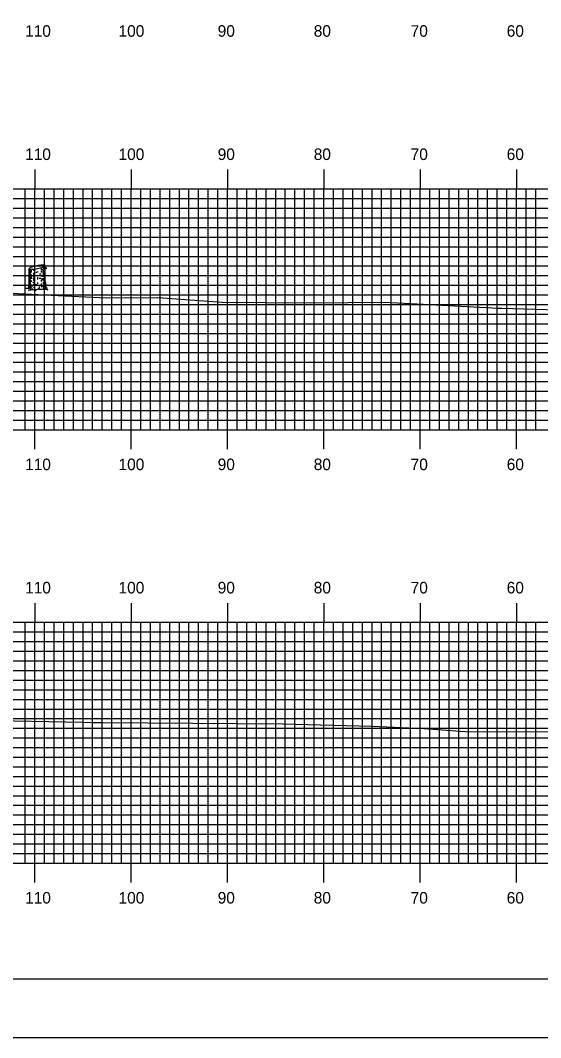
# Model space of a CAD drawing. Extents: x 1772022 to 1772366, y 442591 to 442811.
# Drawn here: x 1772076.6 to 1772130.6, y 442590.5 to 442696.2 of the extents above; entities that cross this region are included whole.
import ezdxf

# ---------------------------------------------------------------- set-up
doc = ezdxf.new("R2010")
doc.units = 0
for name, color, linetype in [('BORDER', 7, 'Continuous'), ('H_V ANNOTATION', 7, 'Continuous'), ('M_Trees_Conifer_Pay', 7, 'Continuous'), ('MAJOR', 7, 'Continuous'), ('MINOR', 7, 'Continuous'), ('PLOT BOUNDARY', 7, 'Continuous'), ('S_Roadway_Centerline', 7, 'Continuous')]:
    doc.layers.add(name, color=color, linetype=linetype)

msp = doc.modelspace()

# ---------------------------------------------------------------- linework, layer by layer
at = {"layer": 'BORDER'}
msp.add_lwpolyline([(1772038.49, 442596.67), (1772358.49, 442596.67), (1772358.49, 442806.67), (1772038.49, 442806.67)], close=True, dxfattribs=at)
at = {"layer": 'M_Trees_Conifer_Pay'}
for p, q in [((1772077.49, 442668.66), (1772077.49, 442670.38)), ((1772077.54, 442670.34), (1772077.54, 442669.87)), ((1772077.59, 442670.33), (1772077.59, 442670.23)), ((1772077.59, 442670.16), (1772077.59, 442669.96)), ((1772077.72, 442670.32), (1772077.72, 442670.09)), ((1772077.72, 442670.05), (1772077.72, 442669.98)), ((1772077.94, 442670.34), (1772077.94, 442670.18)), ((1772078.35, 442670.11), (1772078.35, 442670.02)), ((1772078.74, 442670.39), (1772078.74, 442670.19)), ((1772078.74, 442670.13), (1772078.74, 442670.04)), ((1772078.96, 442670.58), (1772078.96, 442670.36)), ((1772078.96, 442670.27), (1772078.96, 442670.22)), ((1772079.02, 442670.09), (1772078.97, 442670.03)), ((1772079.08, 442670.64), (1772079.08, 442670.48)), ((1772079.08, 442670.41), (1772079.08, 442670.29)), ((1772079.08, 442670.1), (1772079.08, 442669.76)), ((1772079.15, 442669.07), (1772079.15, 442670.72)), ((1772077.54, 442669.81), (1772077.54, 442669.5)), ((1772077.54, 442669.45), (1772077.54, 442668.96)), ((1772077.59, 442669.9), (1772077.59, 442669.7)), ((1772077.59, 442669.65), (1772077.59, 442669.32)), ((1772077.59, 442669.26), (1772077.59, 442669.13)), ((1772077.59, 442669.03), (1772077.59, 442668.65)), ((1772077.72, 442669.57), (1772077.72, 442669.43)), ((1772077.72, 442669.16), (1772077.72, 442669.02)), ((1772077.94, 442669.94), (1772077.94, 442669.7)), ((1772077.94, 442669.46), (1772077.94, 442669.31)), ((1772077.94, 442669.26), (1772077.94, 442669.09)), ((1772078.35, 442669.5), (1772078.35, 442669.42)), ((1772078.35, 442669.4), (1772078.35, 442669.25)), ((1772078.74, 442669.69), (1772078.74, 442669.59)), ((1772078.74, 442669.22), (1772078.74, 442669.07)), ((1772078.96, 442669.89), (1772078.96, 442669.76)), ((1772078.96, 442669.65), (1772078.96, 442669.54)), ((1772078.96, 442669.4), (1772078.96, 442669.26)), ((1772078.96, 442669.03), (1772078.96, 442668.86)), ((1772079.08, 442669.73), (1772079.08, 442669.56)), ((1772079.08, 442669.52), (1772079.08, 442669.3)), ((1772079.08, 442669.27), (1772079.08, 442669.19)), ((1772079.08, 442669.15), (1772079.08, 442668.98)), ((1772077.54, 442668.91), (1772077.54, 442668.66)), ((1772077.72, 442668.76), (1772077.72, 442668.66)), ((1772077.72, 442668.27), (1772077.88, 442668.33)), ((1772077.94, 442668.81), (1772077.94, 442668.66)), ((1772078.16, 442668.2), (1772078.03, 442668.27)), ((1772078.35, 442668.96), (1772078.35, 442668.81)), ((1772078.74, 442668.84), (1772078.74, 442668.75))]:
    msp.add_line(p, q, dxfattribs=at)
for points in [[(1772078.94, 442670.18), (1772078.91, 442670.09), (1772078.9, 442670.02), (1772078.93, 442669.96)], [(1772078.97, 442670.21), (1772079.01, 442670.14), (1772079.05, 442670.2), (1772079.11, 442670.26), (1772079.2, 442670.46), (1772079.27, 442670.51), (1772079.3, 442670.51)], [(1772078.98, 442669.96), (1772079.02, 442670.09), (1772079.08, 442670.2), (1772079.12, 442670.27), (1772079.18, 442670.42)], [(1772079.2, 442670.45), (1772079.27, 442670.45), (1772079.35, 442670.36)], [(1772079.15, 442669.07), (1772079.2, 442668.81), (1772079.22, 442668.53), (1772079.28, 442668.41), (1772079.41, 442668.38), (1772079.18, 442668.34), (1772079.18, 442668.34), (1772079.19, 442668.29), (1772079.44, 442668.2), (1772079.16, 442668.21), (1772078.81, 442668.23), (1772078.49, 442668.22), (1772078.49, 442668.31), (1772078.34, 442668.22), (1772078.16, 442668.2), (1772078.18, 442668.13), (1772077.91, 442668.18), (1772077.69, 442668.15), (1772077.4, 442668.17), (1772077.69, 442668.22), (1772077.72, 442668.27), (1772077.56, 442668.32), (1772077.32, 442668.33), (1772077.08, 442668.33), (1772077.42, 442668.39), (1772077.46, 442668.47), (1772077.49, 442668.66)], [(1772077.67, 442669.69), (1772077.66, 442669.78), (1772077.71, 442669.76), (1772077.71, 442669.66)], [(1772078.81, 442669.29), (1772078.82, 442669.21), (1772078.87, 442669.22), (1772078.85, 442669.39)], [(1772077.54, 442668.61), (1772077.52, 442668.53), (1772077.5, 442668.44)], [(1772077.61, 442668.59), (1772077.62, 442668.48), (1772077.57, 442668.39), (1772077.56, 442668.32)], [(1772077.78, 442668.62), (1772077.78, 442668.49), (1772077.69, 442668.39)], [(1772078, 442668.38), (1772078.07, 442668.47), (1772078.1, 442668.61)], [(1772078.49, 442668.31), (1772078.57, 442668.45), (1772078.58, 442668.55)], [(1772078.74, 442668.68), (1772078.75, 442668.55), (1772078.83, 442668.51)], [(1772079.02, 442668.29), (1772079.01, 442668.42), (1772078.93, 442668.55)], [(1772078.98, 442668.78), (1772079.05, 442668.68), (1772079.06, 442668.5), (1772079.18, 442668.34)], [(1772079.08, 442668.93), (1772079.08, 442668.78), (1772079.13, 442668.71), (1772079.14, 442668.51)]]:
    msp.add_lwpolyline(points, dxfattribs=at)
for centre, radius, start, end in [((1772077.54, 442670.37), 0.0527, 146.7194, 156.5158), ((1772077.52, 442670.38), 0.0314, 156.5158, 169.2194), ((1772077.52, 442670.38), 0.0264, 169.2194, 180.0315), ((1772077.51, 442670.38), 0.0226, 180.0315, 191.7194), ((1772077.51, 442670.38), 0.0226, 191.7194, 203.4074), ((1772077.51, 442670.38), 0.0264, 203.4074, 214.2194), ((1772077.52, 442670.38), 0.0314, 214.2194, 226.923), ((1772077.52, 442670.2), 0.0334, 163.9485, 180), ((1772077.52, 442670.2), 0.0334, 180, 196.0515), ((1772077.53, 442670.2), 0.0441, 196.0515, 210), ((1772077.55, 442670.21), 0.0624, 210, 228.7494), ((1772077.56, 442670.35), 0.0817, 132.3887, 146.7194), ((1772077.53, 442670.4), 0.0527, 226.923, 236.7194), ((1772077.55, 442670.42), 0.0817, 236.7194, 251.0501), ((1772077.68, 442670.23), 0.251, 124.2194, 132.3887), ((1772077.62, 442670.3), 0.172, 228.7494, 240), ((1772077.6, 442670.58), 0.251, 251.0501, 259.2194), ((1772077.82, 442670.64), 0.571, 240, 240.3367), ((1772077.99, 442669.77), 0.802, 108.0594, 124.2194), ((1772077.71, 442671.12), 0.802, 259.2194, 275.3794), ((1772077.82, 442670.64), 0.571, 246.8597, 257.9846), ((1772079.34, 442665.61), 5.18, 101.7194, 108.0594), ((1772077.3, 442675.48), 5.18, 275.3794, 281.7194), ((1772078.32, 442674.39), 4.12, 264.6955, 266.7331), ((1772079.34, 442665.61), 5.18, 95.3794, 101.7194), ((1772077.3, 442675.48), 5.18, 281.7194, 288.0594), ((1772078.32, 442674.16), 4.12, 275.7849, 277.0558), ((1772078.32, 442674.39), 4.12, 276.238, 278.1032), ((1772078.93, 442669.97), 0.802, 79.2194, 95.3794), ((1772078.65, 442671.32), 0.802, 288.0594, 304.2194), ((1772078.82, 442670.87), 0.571, 278.1032, 284.3667), ((1772078.82, 442671.03), 0.571, 284.4317, 292.4132), ((1772079.04, 442670.51), 0.251, 71.0501, 79.2194), ((1772078.82, 442670.87), 0.571, 297.0237, 300), ((1772078.96, 442670.87), 0.251, 304.2194, 312.3887), ((1772079.02, 442670.68), 0.172, 300, 311.2506), ((1772079.02, 442670.53), 0.172, 300, 311.2506), ((1772079.09, 442670.67), 0.0817, 56.7194, 71.0501), ((1772079.08, 442670.74), 0.0817, 312.3887, 326.7194), ((1772079.09, 442670.6), 0.0624, 311.2506, 330), ((1772079.09, 442670.45), 0.0624, 311.2506, 330), ((1772079.11, 442670.7), 0.0527, 46.923, 56.7194), ((1772079.12, 442670.71), 0.0314, 34.2194, 46.923), ((1772079.13, 442670.71), 0.0264, 23.4074, 34.2194), ((1772079.13, 442670.72), 0.0226, 11.7194, 23.4074), ((1772079.13, 442670.72), 0.0264, 349.2194, 0.0315), ((1772079.13, 442670.72), 0.0226, 0.0315, 11.7194), ((1772079.12, 442670.72), 0.0314, 336.5158, 349.2194), ((1772079.1, 442670.73), 0.0527, 326.7194, 336.5158), ((1772079.12, 442670.59), 0.0334, 343.9485, 354.2151), ((1772079.11, 442670.59), 0.0441, 330, 343.9485), ((1772079.11, 442670.44), 0.0441, 330, 343.9485), ((1772079.12, 442670.43), 0.0334, 343.9485, 354.2151), ((1772077.52, 442669.76), 0.0334, 163.9485, 180), ((1772077.52, 442669.76), 0.0334, 180, 196.0515), ((1772077.53, 442669.76), 0.0441, 196.0515, 210), ((1772077.55, 442669.77), 0.0624, 210, 228.7494), ((1772077.52, 442669.55), 0.0334, 163.9485, 180), ((1772077.52, 442669.55), 0.0334, 180, 196.0515), ((1772077.53, 442669.55), 0.0441, 196.0515, 210), ((1772077.55, 442669.56), 0.0624, 210, 228.7494), ((1772077.52, 442669.31), 0.0334, 163.9485, 180), ((1772077.52, 442669.31), 0.0334, 180, 196.0515), ((1772077.53, 442669.31), 0.0441, 196.0515, 210), ((1772077.55, 442669.32), 0.0624, 210, 228.7494), ((1772077.52, 442669.11), 0.0334, 163.9485, 180), ((1772077.62, 442669.85), 0.172, 228.7494, 240), ((1772077.62, 442669.64), 0.172, 228.7494, 240), ((1772077.62, 442669.4), 0.172, 228.7494, 240), ((1772077.82, 442670.43), 0.571, 240, 247.0587), ((1772077.82, 442670.19), 0.571, 240, 240.3367), ((1772077.82, 442669.98), 0.571, 240, 246.8597), ((1772077.82, 442669.75), 0.571, 240, 246.8597), ((1772077.81, 442669.56), 0.571, 241.2369, 248.0268), ((1772077.82, 442669.98), 0.571, 259.2707, 261.8968), ((1772078.32, 442673.5), 4.12, 261.8968, 263.1474), ((1772078.32, 442673.71), 4.12, 264.081, 266.6676), ((1772078.32, 442673.27), 4.12, 264.716, 266.3193), ((1772078.32, 442674.16), 4.12, 268.0751, 270), ((1772078.32, 442674.16), 4.12, 270, 270.3581), ((1772078.32, 442673.5), 4.12, 270, 270.3581), ((1772078.32, 442673.5), 4.12, 273.1493, 275.4569), ((1772078.32, 442673.95), 4.12, 273.7052, 275.9504), ((1772078.32, 442673.71), 4.12, 277.6125, 278.1032), ((1772078.82, 442670.19), 0.571, 278.1032, 286.9296), ((1772078.82, 442670.43), 0.571, 284.4493, 297.0429), ((1772078.82, 442669.75), 0.571, 285.3983, 297.1896), ((1772078.82, 442669.55), 0.571, 289.2907, 300), ((1772078.82, 442670.19), 0.571, 297.1896, 300), ((1772078.82, 442669.98), 0.571, 297.1896, 300), ((1772079.02, 442669.85), 0.172, 300, 311.2506), ((1772079.02, 442669.64), 0.172, 300, 311.2506), ((1772079.02, 442669.21), 0.172, 300, 311.2506), ((1772079.09, 442669.77), 0.0624, 311.2506, 330), ((1772079.09, 442669.56), 0.0624, 311.2506, 330), ((1772079.09, 442669.12), 0.0624, 311.2506, 330), ((1772079.12, 442669.99), 0.0334, 343.9485, 354.2151), ((1772079.11, 442669.76), 0.0441, 330, 343.9485), ((1772079.12, 442669.76), 0.0334, 343.9485, 354.2151), ((1772079.11, 442669.55), 0.0441, 330, 343.9485), ((1772079.12, 442669.55), 0.0334, 343.9485, 354.2151), ((1772079.12, 442669.11), 0.0334, 343.9485, 354.2151), ((1772079.11, 442669.11), 0.0441, 330, 343.9485), ((1772077.52, 442668.92), 0.0334, 163.9485, 180), ((1772077.52, 442668.92), 0.0334, 180, 196.0515), ((1772077.53, 442668.92), 0.0441, 196.0515, 210), ((1772077.55, 442668.93), 0.0624, 210, 228.7494), ((1772077.52, 442668.69), 0.0334, 163.9485, 180), ((1772077.52, 442668.69), 0.0334, 180, 196.0515), ((1772077.53, 442668.7), 0.0441, 196.0515, 210), ((1772077.55, 442668.71), 0.0624, 210, 228.7494), ((1772077.62, 442669.01), 0.172, 228.7494, 240), ((1772077.62, 442668.79), 0.172, 228.7494, 240), ((1772077.82, 442669.35), 0.571, 240, 246.8597), ((1772077.82, 442669.13), 0.571, 240, 244.5314), ((1772078.32, 442672.65), 4.12, 262.4438, 263.512), ((1772078.32, 442673.07), 4.12, 263.4991, 265.8397), ((1772078.32, 442672.87), 4.12, 267.8117, 270), ((1772078.32, 442672.87), 4.12, 270, 270.1328), ((1772078.32, 442672.87), 4.12, 275.7849, 276.7896), ((1772078.32, 442672.65), 4.12, 277.3684, 278.1032), ((1772078.82, 442669.13), 0.571, 278.1032, 281.637), ((1772078.82, 442669.35), 0.571, 288.5067, 297.2721), ((1772079.02, 442668.79), 0.172, 300, 311.2506), ((1772079.09, 442668.71), 0.0624, 311.2506, 330), ((1772079.11, 442668.7), 0.0441, 330, 343.9485), ((1772079.12, 442668.69), 0.0334, 343.9485, 354.2151)]:
    msp.add_arc(centre, radius, start, end, dxfattribs=at)
at = {"layer": 'MAJOR'}
for p, q in [((1772078.09, 442680.67), (1772078.09, 442678.67)), ((1772088.09, 442680.67), (1772088.09, 442678.67)), ((1772098.09, 442680.67), (1772098.09, 442678.67)), ((1772108.09, 442680.67), (1772108.09, 442678.67)), ((1772118.09, 442680.67), (1772118.09, 442678.67)), ((1772128.09, 442680.67), (1772128.09, 442678.67)), ((1772048.09, 442678.67), (1772328.09, 442678.67)), ((1772048.09, 442678.67), (1772328.09, 442678.67)), ((1772078.09, 442653.67), (1772078.09, 442678.67)), ((1772088.09, 442653.67), (1772088.09, 442678.67)), ((1772098.09, 442653.67), (1772098.09, 442678.67)), ((1772108.09, 442653.67), (1772108.09, 442678.67)), ((1772118.09, 442653.67), (1772118.09, 442678.67)), ((1772128.09, 442653.67), (1772128.09, 442678.67)), ((1772048.09, 442673.67), (1772328.09, 442673.67)), ((1772048.09, 442668.67), (1772328.09, 442668.67)), ((1772048.09, 442663.67), (1772328.09, 442663.67)), ((1772048.09, 442658.67), (1772328.09, 442658.67)), ((1772048.09, 442653.67), (1772328.09, 442653.67)), ((1772048.09, 442653.67), (1772328.09, 442653.67)), ((1772078.09, 442651.66), (1772078.09, 442653.67)), ((1772088.09, 442651.66), (1772088.09, 442653.67)), ((1772098.09, 442651.66), (1772098.09, 442653.67)), ((1772108.09, 442651.66), (1772108.09, 442653.67)), ((1772118.09, 442651.66), (1772118.09, 442653.67)), ((1772128.09, 442651.66), (1772128.09, 442653.67)), ((1772078.09, 442635.67), (1772078.09, 442633.67)), ((1772088.09, 442635.67), (1772088.09, 442633.67)), ((1772098.09, 442635.67), (1772098.09, 442633.67)), ((1772108.09, 442635.67), (1772108.09, 442633.67)), ((1772118.09, 442635.67), (1772118.09, 442633.67)), ((1772128.09, 442635.67), (1772128.09, 442633.67)), ((1772048.09, 442633.67), (1772328.09, 442633.67)), ((1772048.09, 442633.67), (1772328.09, 442633.67)), ((1772078.09, 442608.67), (1772078.09, 442633.67)), ((1772088.09, 442608.67), (1772088.09, 442633.67)), ((1772098.09, 442608.67), (1772098.09, 442633.67)), ((1772108.09, 442608.67), (1772108.09, 442633.67)), ((1772118.09, 442608.67), (1772118.09, 442633.67)), ((1772128.09, 442608.67), (1772128.09, 442633.67)), ((1772048.09, 442628.67), (1772328.09, 442628.67)), ((1772048.09, 442623.67), (1772328.09, 442623.67)), ((1772048.09, 442618.67), (1772328.09, 442618.67)), ((1772048.09, 442613.67), (1772328.09, 442613.67)), ((1772048.09, 442608.67), (1772328.09, 442608.67)), ((1772048.09, 442608.67), (1772328.09, 442608.67)), ((1772078.09, 442606.66), (1772078.09, 442608.67)), ((1772088.09, 442606.66), (1772088.09, 442608.67)), ((1772098.09, 442606.66), (1772098.09, 442608.67)), ((1772108.09, 442606.66), (1772108.09, 442608.67)), ((1772118.09, 442606.66), (1772118.09, 442608.67)), ((1772128.09, 442606.66), (1772128.09, 442608.67))]:
    msp.add_line(p, q, dxfattribs=at)
at = {"layer": 'MINOR'}
for p, q in [((1772077.09, 442653.67), (1772077.09, 442678.67)), ((1772079.09, 442653.67), (1772079.09, 442678.67)), ((1772080.09, 442653.67), (1772080.09, 442678.67)), ((1772081.09, 442653.67), (1772081.09, 442678.67)), ((1772082.09, 442653.67), (1772082.09, 442678.67)), ((1772083.09, 442653.67), (1772083.09, 442678.67)), ((1772084.09, 442653.67), (1772084.09, 442678.67)), ((1772085.09, 442653.67), (1772085.09, 442678.67)), ((1772086.09, 442653.67), (1772086.09, 442678.67)), ((1772087.09, 442653.67), (1772087.09, 442678.67)), ((1772089.09, 442653.67), (1772089.09, 442678.67)), ((1772090.09, 442653.67), (1772090.09, 442678.67)), ((1772091.09, 442653.67), (1772091.09, 442678.67)), ((1772092.09, 442653.67), (1772092.09, 442678.67)), ((1772093.09, 442653.67), (1772093.09, 442678.67)), ((1772094.09, 442653.67), (1772094.09, 442678.67)), ((1772095.09, 442653.67), (1772095.09, 442678.67)), ((1772096.09, 442653.67), (1772096.09, 442678.67)), ((1772097.09, 442653.67), (1772097.09, 442678.67)), ((1772099.09, 442653.67), (1772099.09, 442678.67)), ((1772100.09, 442653.67), (1772100.09, 442678.67)), ((1772101.09, 442653.67), (1772101.09, 442678.67)), ((1772102.09, 442653.67), (1772102.09, 442678.67)), ((1772103.09, 442653.67), (1772103.09, 442678.67)), ((1772104.09, 442653.67), (1772104.09, 442678.67)), ((1772105.09, 442653.67), (1772105.09, 442678.67)), ((1772106.09, 442653.67), (1772106.09, 442678.67)), ((1772107.09, 442653.67), (1772107.09, 442678.67)), ((1772109.09, 442653.67), (1772109.09, 442678.67)), ((1772110.09, 442653.67), (1772110.09, 442678.67)), ((1772111.09, 442653.67), (1772111.09, 442678.67)), ((1772112.09, 442653.67), (1772112.09, 442678.67)), ((1772113.09, 442653.67), (1772113.09, 442678.67)), ((1772114.09, 442653.67), (1772114.09, 442678.67)), ((1772115.09, 442653.67), (1772115.09, 442678.67)), ((1772116.09, 442653.67), (1772116.09, 442678.67)), ((1772117.09, 442653.67), (1772117.09, 442678.67)), ((1772119.09, 442653.67), (1772119.09, 442678.67)), ((1772120.09, 442653.67), (1772120.09, 442678.67)), ((1772121.09, 442653.67), (1772121.09, 442678.67)), ((1772122.09, 442653.67), (1772122.09, 442678.67)), ((1772123.09, 442653.67), (1772123.09, 442678.67)), ((1772124.09, 442653.67), (1772124.09, 442678.67)), ((1772125.09, 442653.67), (1772125.09, 442678.67)), ((1772126.09, 442653.67), (1772126.09, 442678.67)), ((1772127.09, 442653.67), (1772127.09, 442678.67)), ((1772129.09, 442653.67), (1772129.09, 442678.67)), ((1772130.09, 442653.67), (1772130.09, 442678.67)), ((1772048.09, 442677.67), (1772328.09, 442677.67)), ((1772048.09, 442676.67), (1772328.09, 442676.67)), ((1772048.09, 442675.67), (1772328.09, 442675.67)), ((1772048.09, 442674.67), (1772328.09, 442674.67)), ((1772048.09, 442672.67), (1772328.09, 442672.67)), ((1772048.09, 442671.67), (1772328.09, 442671.67)), ((1772048.09, 442670.67), (1772328.09, 442670.67)), ((1772048.09, 442669.67), (1772328.09, 442669.67)), ((1772048.09, 442667.67), (1772328.09, 442667.67)), ((1772048.09, 442666.67), (1772328.09, 442666.67)), ((1772048.09, 442665.67), (1772328.09, 442665.67)), ((1772048.09, 442664.67), (1772328.09, 442664.67)), ((1772048.09, 442662.67), (1772328.09, 442662.67)), ((1772048.09, 442661.67), (1772328.09, 442661.67)), ((1772048.09, 442660.67), (1772328.09, 442660.67)), ((1772048.09, 442659.67), (1772328.09, 442659.67)), ((1772048.09, 442657.67), (1772328.09, 442657.67)), ((1772048.09, 442656.67), (1772328.09, 442656.67)), ((1772048.09, 442655.67), (1772328.09, 442655.67)), ((1772048.09, 442654.67), (1772328.09, 442654.67)), ((1772077.09, 442608.67), (1772077.09, 442633.67)), ((1772079.09, 442608.67), (1772079.09, 442633.67)), ((1772080.09, 442608.67), (1772080.09, 442633.67)), ((1772081.09, 442608.67), (1772081.09, 442633.67)), ((1772082.09, 442608.67), (1772082.09, 442633.67)), ((1772083.09, 442608.67), (1772083.09, 442633.67)), ((1772084.09, 442608.67), (1772084.09, 442633.67)), ((1772085.09, 442608.67), (1772085.09, 442633.67)), ((1772086.09, 442608.67), (1772086.09, 442633.67)), ((1772087.09, 442608.67), (1772087.09, 442633.67)), ((1772089.09, 442608.67), (1772089.09, 442633.67)), ((1772090.09, 442608.67), (1772090.09, 442633.67)), ((1772091.09, 442608.67), (1772091.09, 442633.67)), ((1772092.09, 442608.67), (1772092.09, 442633.67)), ((1772093.09, 442608.67), (1772093.09, 442633.67)), ((1772094.09, 442608.67), (1772094.09, 442633.67)), ((1772095.09, 442608.67), (1772095.09, 442633.67)), ((1772096.09, 442608.67), (1772096.09, 442633.67)), ((1772097.09, 442608.67), (1772097.09, 442633.67)), ((1772099.09, 442608.67), (1772099.09, 442633.67)), ((1772100.09, 442608.67), (1772100.09, 442633.67)), ((1772101.09, 442608.67), (1772101.09, 442633.67)), ((1772102.09, 442608.67), (1772102.09, 442633.67)), ((1772103.09, 442608.67), (1772103.09, 442633.67)), ((1772104.09, 442608.67), (1772104.09, 442633.67)), ((1772105.09, 442608.67), (1772105.09, 442633.67)), ((1772106.09, 442608.67), (1772106.09, 442633.67)), ((1772107.09, 442608.67), (1772107.09, 442633.67)), ((1772109.09, 442608.67), (1772109.09, 442633.67)), ((1772110.09, 442608.67), (1772110.09, 442633.67)), ((1772111.09, 442608.67), (1772111.09, 442633.67)), ((1772112.09, 442608.67), (1772112.09, 442633.67)), ((1772113.09, 442608.67), (1772113.09, 442633.67)), ((1772114.09, 442608.67), (1772114.09, 442633.67)), ((1772115.09, 442608.67), (1772115.09, 442633.67)), ((1772116.09, 442608.67), (1772116.09, 442633.67)), ((1772117.09, 442608.67), (1772117.09, 442633.67)), ((1772119.09, 442608.67), (1772119.09, 442633.67)), ((1772120.09, 442608.67), (1772120.09, 442633.67)), ((1772121.09, 442608.67), (1772121.09, 442633.67)), ((1772122.09, 442608.67), (1772122.09, 442633.67)), ((1772123.09, 442608.67), (1772123.09, 442633.67)), ((1772124.09, 442608.67), (1772124.09, 442633.67)), ((1772125.09, 442608.67), (1772125.09, 442633.67)), ((1772126.09, 442608.67), (1772126.09, 442633.67)), ((1772127.09, 442608.67), (1772127.09, 442633.67)), ((1772129.09, 442608.67), (1772129.09, 442633.67)), ((1772130.09, 442608.67), (1772130.09, 442633.67)), ((1772048.09, 442632.67), (1772328.09, 442632.67)), ((1772048.09, 442631.67), (1772328.09, 442631.67)), ((1772048.09, 442630.67), (1772328.09, 442630.67)), ((1772048.09, 442629.67), (1772328.09, 442629.67)), ((1772048.09, 442627.67), (1772328.09, 442627.67)), ((1772048.09, 442626.67), (1772328.09, 442626.67)), ((1772048.09, 442625.67), (1772328.09, 442625.67)), ((1772048.09, 442624.67), (1772328.09, 442624.67)), ((1772048.09, 442622.67), (1772328.09, 442622.67)), ((1772048.09, 442621.67), (1772328.09, 442621.67)), ((1772048.09, 442620.67), (1772328.09, 442620.67)), ((1772048.09, 442619.67), (1772328.09, 442619.67)), ((1772048.09, 442617.67), (1772328.09, 442617.67)), ((1772048.09, 442616.67), (1772328.09, 442616.67)), ((1772048.09, 442615.67), (1772328.09, 442615.67)), ((1772048.09, 442614.67), (1772328.09, 442614.67)), ((1772048.09, 442612.67), (1772328.09, 442612.67)), ((1772048.09, 442611.67), (1772328.09, 442611.67)), ((1772048.09, 442610.67), (1772328.09, 442610.67)), ((1772048.09, 442609.67), (1772328.09, 442609.67))]:
    msp.add_line(p, q, dxfattribs=at)
at = {"layer": 'PLOT BOUNDARY'}
msp.add_lwpolyline([(1772022.31, 442590.55), (1772362.31, 442590.55), (1772362.31, 442810.55), (1772022.31, 442810.55)], close=True, dxfattribs=at)
at = {"layer": 'S_Roadway_Centerline'}
for points in [[(1772048.09, 442669.44), (1772056.43, 442668.95), (1772066.45, 442668.45), (1772068.51, 442668.25), (1772071.6, 442668.05), (1772079.78, 442667.65), (1772085.53, 442667.35), (1772090.85, 442667.41), (1772097.53, 442666.92), (1772106.7, 442666.85), (1772114.44, 442666.92), (1772125.59, 442666.32), (1772126.18, 442666.3), (1772126.59, 442666.3), (1772137.91, 442665.93)], [(1772048.09, 442624.09), (1772048.65, 442624.07), (1772056.92, 442623.94), (1772060.34, 442623.83), (1772062.54, 442623.77), (1772072.43, 442623.51), (1772083.06, 442623.31), (1772084.03, 442623.27), (1772085.16, 442623.26), (1772103.83, 442623.12), (1772107.74, 442623.01), (1772113.07, 442622.88), (1772118.47, 442622.63), (1772122.77, 442622.34), (1772139.06, 442622.29)]]:
    msp.add_lwpolyline(points, dxfattribs=at)

# ---------------------------------------------------------------- texts
at = {"layer": 'H_V ANNOTATION'}
for s, p in [('110', (1772077.08, 442694.47)), ('100', (1772086.78, 442694.47)), ('90', (1772097.07, 442694.47)), ('80', (1772107.04, 442694.47)), ('70', (1772117.1, 442694.47)), ('60', (1772127.07, 442694.47)), ('110', (1772077.08, 442681.67)), ('100', (1772086.78, 442681.67)), ('90', (1772097.07, 442681.67)), ('80', (1772107.04, 442681.67)), ('70', (1772117.1, 442681.67)), ('60', (1772127.07, 442681.67)), ('110', (1772077.08, 442649.47)), ('100', (1772086.78, 442649.47)), ('90', (1772097.07, 442649.47)), ('80', (1772107.04, 442649.47)), ('70', (1772117.1, 442649.47)), ('60', (1772127.07, 442649.47)), ('110', (1772077.08, 442636.67)), ('100', (1772086.78, 442636.67)), ('90', (1772097.07, 442636.67)), ('80', (1772107.04, 442636.67)), ('70', (1772117.1, 442636.67)), ('60', (1772127.07, 442636.67)), ('110', (1772077.08, 442604.47)), ('100', (1772086.78, 442604.47)), ('90', (1772097.07, 442604.47)), ('80', (1772107.04, 442604.47)), ('70', (1772117.1, 442604.47)), ('60', (1772127.07, 442604.47))]:
    msp.add_text(s, height=1.2, dxfattribs=at).set_placement(p)

doc.saveas('drawing.dxf')
